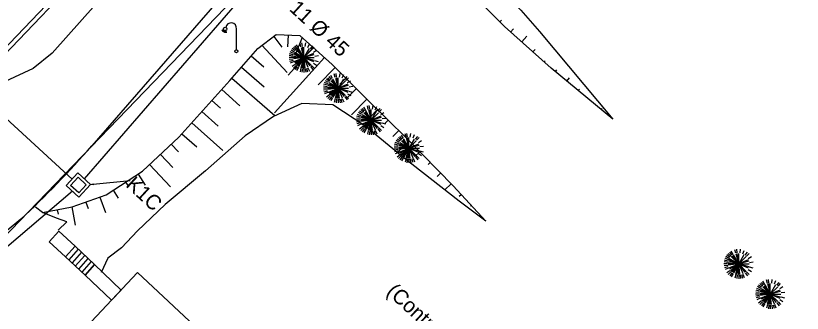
# Model space of a CAD drawing. Extents: x 343997 to 344255, y 298512 to 298767.
# Drawn here: x 344122.6 to 344175.3, y 298618.2 to 298638.2 of the extents above; entities that cross this region are included whole.
import ezdxf

# ---------------------------------------------------------------- set-up
doc = ezdxf.new("R2010")
doc.units = 0
for name, color, linetype in [('Commentaires', 7, 'Continuous'), ('Default', 7, 'Continuous'), ('DH_CADRE-CARTOUCHE', 7, 'Continuous'), ('DIR-Projet VRD1', 7, 'Continuous'), ('GO_DALLE', 7, 'Continuous'), ('GO_ESCALIER', 7, 'Continuous'), ('O-Projet New VRD', 7, 'Continuous'), ('OPT VRD', 7, 'Continuous'), ('PC_REBAR', 7, 'Continuous'), ('PS_OBJECT', 7, 'Continuous'), ('RES_ELECTRICITE', 7, 'Continuous')]:
    doc.layers.add(name, color=color, linetype=linetype)

# ---------------------------------------------------------------- blocks, each defined once
blk = doc.blocks.new('EDF1')
at = {"layer": 'Default'}
for points in [[(-0.0855, 0.1462), (-0.0985, 0.1373)], [(-0.083, 0.1422), (-0.0931, 0.1303)], [(-0.0793, 0.1397), (-0.086, 0.1257)], [(-0.0753, 0.1388), (-0.0781, 0.1235)], [(-0.0701, 0.14), (-0.0684, 0.1241)], [(0, 0.01), (0, 0.15)]]:
    blk.add_lwpolyline(points, dxfattribs=at)
for centre, radius in [((-0.075, 0.15), 0.0112), ((0, 0), 0.01)]:
    blk.add_circle(centre, radius, dxfattribs=at)
blk.add_arc((-0.035, 0.155), 0.0354, 351.8699, 171.8699, dxfattribs=at)
blk = doc.blocks.new('ARB2')
at = {"layer": 'Default'}
for p, q in [((-0.0575, 0.0453), (-0.0775, 0.0605)), ((-0.0513, 0.0525), (-0.0688, 0.0702)), ((-0.0438, 0.0589), (-0.0588, 0.0786)), ((-0.0356, 0.0642), (-0.0481, 0.0858)), ((-0.0181, 0.0716), (-0.0244, 0.0956)), ((-0.0088, 0.0736), (-0.0119, 0.0983)), ((0.0106, 0.0736), (0.0144, 0.0983)), ((0.0287, 0.0684), (0.0388, 0.0914)), ((0.0456, 0.0589), (0.0612, 0.0786)), ((0.0531, 0.0525), (0.0706, 0.0702)), ((-0.0731, 0), (-0.0981, 0)), ((-0.0725, 0.01), (-0.0969, 0.0133)), ((-0.0706, 0.0195), (-0.0944, 0.0259)), ((-0.0675, 0.0286), (-0.09, 0.0381)), ((-0.0631, 0.0373), (-0.0844, 0.0497)), ((0.065, 0.0373), (0.0862, 0.0497)), ((0.0744, 0.01), (0.0987, 0.0133)), ((-0.0725, -0.01), (-0.0969, -0.0133)), ((-0.0706, -0.0195), (-0.0944, -0.0259)), ((-0.0675, -0.0287), (-0.09, -0.0383)), ((-0.0575, -0.0455), (-0.0775, -0.0605)), ((-0.0513, -0.0527), (-0.0688, -0.0702)), ((0.0531, -0.0527), (0.0706, -0.0702)), ((0.065, -0.0373), (0.0862, -0.0498)), ((0.0725, -0.0195), (0.0963, -0.0259)), ((-0.0438, -0.0591), (-0.0588, -0.0787)), ((-0.0356, -0.0644), (-0.0481, -0.0859)), ((-0.0181, -0.0717), (-0.0244, -0.0956)), ((-0.0088, -0.0737), (-0.0119, -0.0983)), ((0.0013, -0.0741), (0.0013, -0.0989)), ((0.0106, -0.0737), (0.0144, -0.0983)), ((0.02, -0.0717), (0.0263, -0.0956)), ((0.0287, -0.0686), (0.0388, -0.0916)), ((0.0456, -0.0591), (0.0612, -0.0787))]:
    blk.add_line(p, q, dxfattribs=at)
for points in [[(-0.0688, 0.0091), (0.0013, 0), (-0.0338, 0.0608)], [(-0.0419, 0.0556), (0.0013, 0), (-0.0638, 0.0269)], [(-0.0169, 0.0677), (0.0013, 0), (-0.06, 0.035)], [(0.0013, 0.0008), (0.0013, 0), (-0.0081, 0.0695)], [(0.0362, 0.0608), (0.0013, 0), (0.0013, 0.0702)], [(-0.0487, -0.0497), (0.0013, 0), (-0.0694, 0)], [(-0.0638, -0.0269), (0.0013, 0), (-0.0688, -0.0092)], [(-0.0487, 0.0495), (0.0013, 0), (-0.0669, 0.0181)], [(-0.0169, -0.0678), (0.0013, 0), (-0.06, -0.0352)], [(-0.0544, -0.0428), (0.0013, 0), (-0.0338, -0.0608)], [(-0.0081, -0.0695), (0.0013, 0), (-0.0419, -0.0558)], [(0.0013, -0.0702), (0.0013, 0), (0, 0)], [(0.0656, 0.0269), (0.0013, 0), (0.0506, 0.0495)], [(0.0688, 0.0181), (0.0013, 0), (0.0713, 0)], [(0.0438, -0.0558), (0.0013, 0), (0.0656, -0.0269)], [(0.0506, -0.0497), (0.0013, 0), (0.0688, -0.0181)], [(0.01, -0.0695), (0.0013, 0), (0.0281, -0.0648)], [(0.0019, 0), (0.0013, 0), (0.0013, -0.0009)]]:
    blk.add_lwpolyline(points, dxfattribs=at)
blk = doc.blocks.new('K1C')
at = {"layer": 'Default'}
for points in [[(35083.6085, 29821.5636), (35083.7239, 29821.5636), (35083.7239, 29821.6785), (35083.6085, 29821.6785)], [(35083.6287, 29821.6586), (35083.7037, 29821.6586), (35083.7037, 29821.5836), (35083.6287, 29821.5836)]]:
    blk.add_lwpolyline(points, close=True, dxfattribs=at)
for points in [[(35083.7037, 29821.6586), (35083.7039, 29821.6585)], [(35083.6085, 29821.5637), (35083.6087, 29821.5636)]]:
    blk.add_lwpolyline(points, dxfattribs=at)

msp = doc.modelspace()

# ---------------------------------------------------------------- linework, layer by layer
at = {"layer": 'DH_CADRE-CARTOUCHE'}
for points in [[(344124.372, 298692.186), (344148.812, 298670.333), (344149.478, 298669.504), (344150.054, 298668.628), (344150.475, 298667.688), (344150.721, 298667.085), (344151.432, 298665.306), (344151.673, 298664.395), (344151.676, 298663.909), (344143.5, 298656.169), (344142.683, 298655.44), (344135.602, 298647.623), (344124.992, 298635.682), (344123.722, 298634.656), (344121.833, 298633.77), (344119.792, 298633.516), (344117.727, 298633.77), (344116.3, 298634.425), (344115.03, 298635.389), (344091.665, 298656.941), (344066.817, 298679.859)], [(344079.116, 298659.278), (344094.724, 298644.749), (344120.412, 298621.951), (344137.791, 298639.981), (344144.065, 298646.663), (344154.783, 298657.656), (344157.662, 298660.576), (344158.342, 298661.39), (344163.216, 298666.766), (344163.731, 298667.308), (344164.688, 298668.072), (344165.676, 298668.545), (344166.447, 298668.825), (344167.222, 298669.059), (344168.509, 298669.289), (344169.751, 298669.392), (344170.251, 298669.414), (344170.803, 298669.375), (344172.06, 298669.227), (344173.884, 298668.877), (344175.641, 298668.318)]]:
    msp.add_lwpolyline(points, dxfattribs=at)
at = {"layer": 'DIR-Projet VRD1'}
for p, q in [((344161.215, 298666.549), (344127.144, 298627.25)), ((344105.347, 298646.566), (344126.33, 298627.218)), ((344126.364, 298626.406), (344111.814, 298614.103))]:
    msp.add_line(p, q, dxfattribs=at)
at = {"layer": 'GO_DALLE'}
for points in [[(344125.438, 298623.737), (344124.804, 298623.015), (344125.891, 298622.006), (344126.526, 298622.728)], [(344127.203, 298620.772), (344128.981, 298619.099), (344129.629, 298619.779), (344127.831, 298621.487)]]:
    msp.add_lwpolyline(points, close=True, dxfattribs=at)
msp.add_lwpolyline([(344173.444, 298593.641), (344172.427, 298592.568), (344178.462, 298586.939), (344174.396, 298582.587), (344168.376, 298588.228), (344167.085, 298586.853), (344168.386, 298585.586), (344159.324, 298576.069), (344121.411, 298611.054), (344130.716, 298620.945), (344149.461, 298603.379), (344147.717, 298601.519)], dxfattribs=at)
at = {"layer": 'GO_ESCALIER'}
msp.add_lwpolyline([(344125.891, 298622.006), (344127.203, 298620.772), (344127.831, 298621.487), (344126.526, 298622.728)], close=True, dxfattribs=at)
for points in [[(344126.743, 298622.521), (344126.11, 298621.8)], [(344126.961, 298622.315), (344126.329, 298621.594)], [(344127.178, 298622.108), (344126.547, 298621.389)], [(344127.396, 298621.901), (344126.766, 298621.183)], [(344127.614, 298621.694), (344126.984, 298620.977)]]:
    msp.add_lwpolyline(points, dxfattribs=at)
at = {"layer": 'O-Projet New VRD'}
msp.add_lwpolyline([(344127.747, 298626.877), (344130.222, 298627.125)], dxfattribs=at)
msp.add_lwpolyline([(344127.75, 298626.847), (344127.568, 298626.859), (344127.744, 298626.907)], close=True, dxfattribs=at)
at = {"layer": 'OPT VRD'}
for points in [[(344154.293, 298660.137), (344127.646, 298629.457)], [(344122.894, 298624.526), (344110.021, 298613.871)]]:
    msp.add_lwpolyline(points, dxfattribs=at)
msp.add_arc((344077.801, 298672.748), 66.02, 313.07921, 319.02493, dxfattribs=at)
at = {"layer": 'PC_REBAR'}
msp.add_lwpolyline([(344129.915, 298683.811), (344149.954, 298665.484), (344120.649, 298634.816), (344119.758, 298634.843), (344094.693, 298657.614), (344119.626, 298684.533), (344119.467, 298684.803), (344094.267, 298657.595), (344119.638, 298634.546), (344120.774, 298634.512), (344150.383, 298665.499), (344130.117, 298684.033)], close=True, dxfattribs=at)
at = {"layer": 'PS_OBJECT'}
for p, q in [((344155.011, 298637.777), (344155.136, 298637.902)), ((344155.741, 298637.094), (344155.94, 298637.319)), ((344139.855, 298636.805), (344140.397, 298636.076)), ((344140.813, 298636.897), (344140.78, 298636.113)), ((344141.761, 298636.73), (344141.289, 298635.572)), ((344156.489, 298636.43), (344156.83, 298636.814)), ((344139.052, 298636.207), (344140.755, 298634.376)), ((344142.504, 298636.061), (344140.83, 298634.203)), ((344138.347, 298635.505), (344139.198, 298634.769)), ((344157.237, 298635.766), (344157.383, 298635.93)), ((344143.247, 298635.391), (344139.9, 298631.675)), ((344157.985, 298635.101), (344158.047, 298635.172)), ((344137.693, 298634.749), (344139.218, 298633.43)), ((344143.98, 298634.711), (344142.822, 298633.548)), ((344158.74, 298634.446), (344158.843, 298634.57)), ((344137.039, 298633.992), (344139.935, 298631.487)), ((344144.689, 298634.005), (344144.289, 298633.603)), ((344159.509, 298633.807), (344159.685, 298634.018)), ((344136.373, 298633.246), (344137.589, 298632.152)), ((344145.397, 298633.299), (344144.783, 298632.682)), ((344160.278, 298633.167), (344160.353, 298633.257)), ((344135.704, 298632.502), (344136.281, 298631.982)), ((344146.106, 298632.593), (344145.064, 298631.537)), ((344161.048, 298632.527), (344161.08, 298632.566)), ((344146.818, 298631.891), (344146.324, 298631.39)), ((344161.817, 298631.888), (344161.871, 298631.954)), ((344135.035, 298631.758), (344136.132, 298630.771)), ((344134.366, 298631.014), (344136.45, 298629.14)), ((344147.531, 298631.188), (344147.32, 298630.975)), ((344133.697, 298630.271), (344134.687, 298629.381)), ((344148.243, 298630.486), (344147.843, 298630.081)), ((344148.952, 298629.781), (344148.179, 298629.03)), ((344132.986, 298629.569), (344133.466, 298629.057)), ((344132.257, 298628.884), (344133.078, 298628.009)), ((344149.649, 298629.064), (344149.32, 298628.743)), ((344131.527, 298628.199), (344132.932, 298626.703)), ((344150.347, 298628.346), (344150.206, 298628.21)), ((344151.044, 298627.629), (344150.804, 298627.396)), ((344130.76, 298627.563), (344131.238, 298626.827)), ((344129.921, 298627.018), (344130.125, 298626.704)), ((344151.741, 298626.912), (344151.332, 298626.514)), ((344128.199, 298626.02), (344128.565, 298624.988)), ((344129.082, 298626.473), (344129.431, 298625.936)), ((344152.423, 298626.18), (344152.279, 298626.047)), ((344127.256, 298625.685), (344127.412, 298625.244)), ((344125.329, 298625.169), (344125.386, 298624.866)), ((344126.312, 298625.353), (344126.543, 298624.124)), ((344153.102, 298625.446), (344153.057, 298625.404)), ((344153.781, 298624.711), (344153.754, 298624.686))]:
    msp.add_line(p, q, dxfattribs=at)
for points in [[(344162.586, 298631.249), (344158.463, 298634.677), (344155.322, 298637.466), (344152.157, 298640.641), (344150.03, 298642.712), (344148.876, 298643.869), (344148.225, 298645.042), (344148.989, 298646.167), (344150.999, 298648.31), (344152.976, 298650.281), (344154.876, 298652.174), (344156.31, 298653.84), (344157.421, 298655.01), (344158.446, 298655.921), (344159.147, 298656.242), (344160.098, 298656.281)], [(344160.098, 298656.281), (344158.45, 298653.962), (344154.227, 298648.857), (344151.775, 298646.036), (344151.324, 298644.439), (344151.952, 298643.242), (344152.321, 298642.95), (344152.643, 298643.115), (344152.674, 298642.658), (344154.315, 298640.791), (344156.42, 298638.569), (344157.669, 298637.128), (344162.586, 298631.249)], [(344124.346, 298624.984), (344126.33, 298625.357), (344128.607, 298626.165), (344131.049, 298627.75), (344133.499, 298630.05), (344136.91, 298633.844), (344138.778, 298636.003), (344140.023, 298636.93), (344141.613, 298636.864), (344143.764, 298634.926), (344146.016, 298632.683), (344148.833, 298629.903), (344151.879, 298626.77), (344154.069, 298624.399)], [(344154.069, 298624.399), (344152.293, 298625.755), (344148.595, 298628.63), (344145.956, 298630.806), (344143.812, 298632.217), (344141.743, 298632.29), (344139.831, 298631.436), (344137.933, 298630.141), (344135.272, 298627.787), (344132.577, 298625.511), (344130.725, 298623.759), (344129.654, 298622.612), (344128.717, 298621.914), (344128.286, 298620.948)], [(344125.982, 298624.352), (344125.282, 298624.613), (344124.346, 298624.984), (344123.867, 298625.338)], [(344125.396, 298623.8), (344125.982, 298624.352)]]:
    msp.add_lwpolyline(points, dxfattribs=at)

# ---------------------------------------------------------------- block references
at = {"layer": 'O-Projet New VRD', "xscale": 10, "yscale": 10, "rotation": -42.63277399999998}
msp.add_blockref('K1C', (-115968.13, 316846.832), dxfattribs=at)
at = {"layer": 'PC_REBAR', "xscale": 10, "yscale": 10}
for p in [(344141.861, 298635.381), (344144.161, 298633.329), (344146.378, 298631.19), (344148.907, 298629.309), (344171.021, 298621.529), (344173.142, 298619.509)]:
    msp.add_blockref('ARB2', p, dxfattribs=at)
at = {"layer": 'RES_ELECTRICITE', "xscale": 10, "yscale": 10}
msp.add_blockref('EDF1', (344137.347, 298635.809), dxfattribs=at)

# ---------------------------------------------------------------- texts
at = {"layer": 'Commentaires'}
msp.add_text("(Contrôle de câble - mesure d'isolement)", height=1.00027, rotation=317.3672, dxfattribs=at).set_placement((344147.356, 298619.58))
at = {"layer": 'O-Projet New VRD'}
for s, p in [('11 Ø 45', (344140.838, 298638.586)), ('K1C', (344129.873, 298626.767))]:
    msp.add_text(s, height=1.0003, rotation=317.3672, dxfattribs=at).set_placement(p)

doc.saveas('drawing.dxf')
